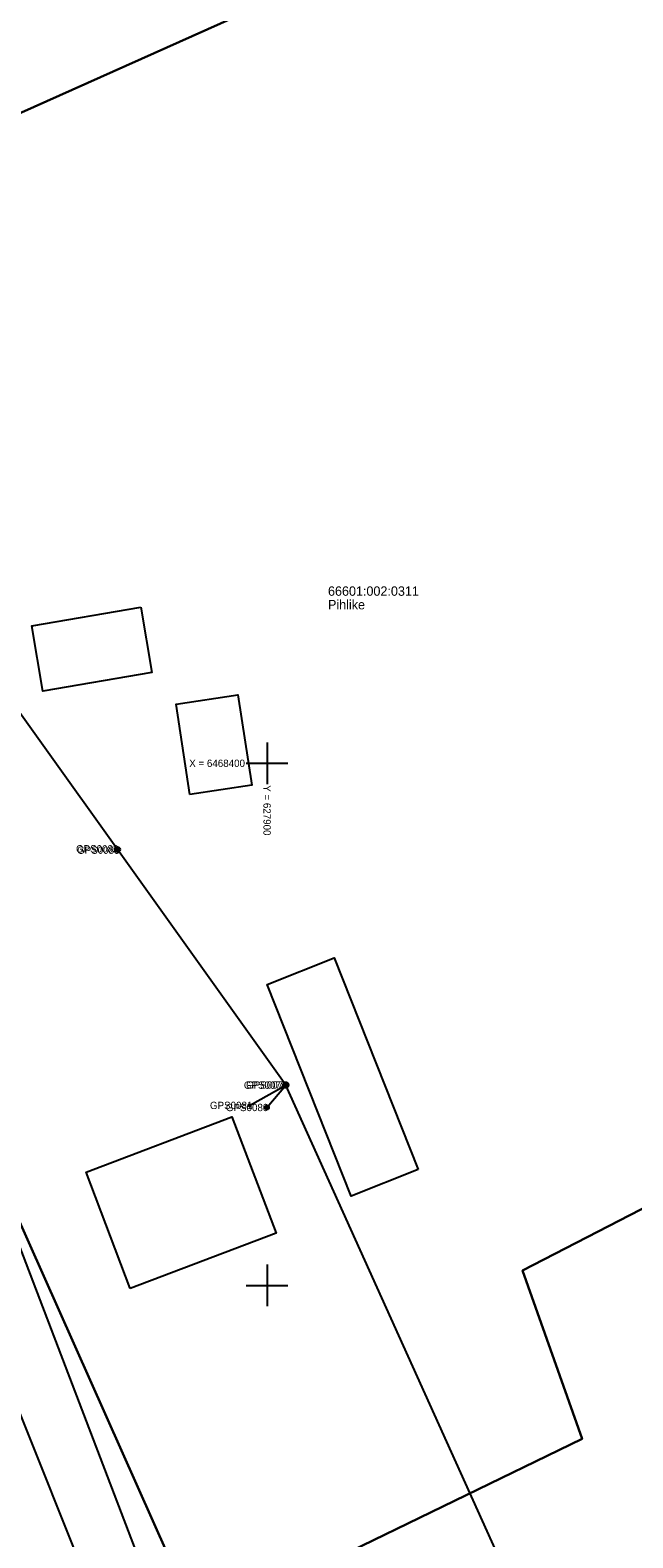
# Model space of a CAD drawing. Extents: x 626224 to 628280, y 6467750 to 6471135.
# Drawn here: x 627877.3 to 627935, y 6468325.8 to 6468470.2 of the extents above; entities that cross this region are included whole.
import ezdxf

# ---------------------------------------------------------------- set-up
doc = ezdxf.new("R2010")
doc.units = 0
for name, color, linetype in [('Hoone Elu- või ühiskondlik hoone', 7, 'Continuous'), ('Hoone Kõrval- või tootmishoone', 7, 'Continuous'), ('Maa-alune hoone Kelder', 7, 'Continuous'), ('MOOTMPUNKT', 7, 'Continuous'), ('MOOTNR', 7, 'Continuous'), ('MPOHULIIN', 7, 'Continuous'), ('PIIR', 7, 'Continuous'), ('POST', 7, 'Continuous'), ('Tee Liiklusala', 7, 'Continuous'), ('Tee Põhimaantee Püsikate', 7, 'Continuous'), ('VORK', 7, 'Continuous')]:
    doc.layers.add(name, color=color, linetype=linetype)

msp = doc.modelspace()

# ---------------------------------------------------------------- linework, layer by layer
at = {"layer": 'Hoone Elu- või ühiskondlik hoone'}
msp.add_lwpolyline([(627886.91, 6468349.7), (627882.67, 6468360.85), (627896.64, 6468366.16), (627900.87, 6468354.99)], close=True, dxfattribs=at)
at = {"layer": 'Hoone Kõrval- või tootmishoone'}
for points in [[(627887.9, 6468414.95), (627888.97, 6468408.69), (627878.55, 6468406.91), (627877.47, 6468413.16)], [(627914.47, 6468361.1), (627908.04, 6468358.55), (627900, 6468378.81), (627906.43, 6468381.36)]]:
    msp.add_lwpolyline(points, close=True, dxfattribs=at)
at = {"layer": 'Maa-alune hoone Kelder'}
msp.add_lwpolyline([(627892.59, 6468397.01), (627891.3, 6468405.67), (627897.21, 6468406.57), (627898.53, 6468397.91)], close=True, dxfattribs=at)
at = {"layer": 'MOOTMPUNKT'}
for centre in [(627885.63, 6468391.81), (627885.73, 6468391.68), (627901.7, 6468369.18), (627901.91, 6468369.2), (627898.31, 6468367.24), (627899.98, 6468367.04)]:
    msp.add_circle(centre, 0.1, dxfattribs=at)
at = {"layer": 'MPOHULIIN'}
msp.add_line((627898.31, 6468367.24), (627901.8, 6468369.19), dxfattribs=at)
msp.add_lwpolyline([(627987.7, 6468154.84), (627974.22, 6468199.23), (627965.02, 6468229.51), (627942.94, 6468278.29), (627925.23, 6468317.29), (627901.8, 6468369.19), (627885.68, 6468391.75), (627864.62, 6468421.17)], dxfattribs=at)
at = {"layer": 'PIIR'}
for points in [[(627932.6, 6468557.07), (627965.68, 6468502.25), (627838.09, 6468445.14), (627818.92, 6468478.42), (627816.33, 6468482.77), (627807.45, 6468497.75)], [(627965.68, 6468502.25), (628025.29, 6468403.44), (627924.44, 6468351.42), (627930.15, 6468335.32), (627893.5, 6468317.49), (627836.88, 6468444.6), (627838.09, 6468445.14)], [(627930.15, 6468335.32), (627924.44, 6468351.42), (628025.29, 6468403.44), (628093.6, 6468443.97), (628137.33, 6468332.21), (628082.32, 6468314.62), (628013.29, 6468289.31), (627952.14, 6468288.19), (627947, 6468286.53), (627948.23, 6468284.28), (627912.59, 6468271.79), (627893.5, 6468317.49)]]:
    msp.add_lwpolyline(points, close=True, dxfattribs=at)
msp.add_lwpolyline([(627869.05, 6468319.44), (627860.61, 6468341.12), (627850.92, 6468363.47), (627843.3, 6468381.02), (627834.21, 6468400.21), (627826.02, 6468416.53), (627816.81, 6468434.6), (627809.58, 6468448), (627801.28, 6468461.34), (627796.62, 6468466.91), (627793.68, 6468471.35), (627793.54, 6468471.56), (627816.33, 6468482.77), (627818.92, 6468478.42), (627838.09, 6468445.14), (627836.88, 6468444.6), (627893.5, 6468317.49)], dxfattribs=at)
at = {"layer": 'POST'}
msp.add_lwpolyline([(627899.98, 6468367.04), (627901.8, 6468369.19)], dxfattribs=at)
for centre, radius in [((627885.68, 6468391.75), 0.25), ((627885.68, 6468391.75), 0.0234), ((627901.8, 6468369.19), 0.25), ((627901.8, 6468369.19), 0.0234), ((627899.98, 6468367.04), 0.2)]:
    msp.add_circle(centre, radius, dxfattribs=at)
at = {"layer": 'Tee Liiklusala'}
msp.add_lwpolyline([(627760.92, 6468560.36), (627780.56, 6468531.91), (627795.19, 6468507.83), (627804.8, 6468492.03), (627819.21, 6468468.28), (627829.48, 6468450.66), (627842.63, 6468424.88), (627852.37, 6468405.79), (627854.86, 6468400.94), (627874.21, 6468359.17), (627891.81, 6468313.11), (627897.89, 6468298.46), (627907.18, 6468276.08), (627914.22, 6468258.33), (627924.31, 6468232.91), (627926.05, 6468227.94), (627930.17, 6468216.22), (627939.76, 6468188.97), (627954.88, 6468146.07), (627973.91, 6468092.36), (627984.64, 6468061.12)], dxfattribs=at)
at = {"layer": 'Tee Põhimaantee Püsikate'}
msp.add_lwpolyline([(627812.12, 6468468.85), (627818.26, 6468457.76), (627833.15, 6468430.27), (627849.46, 6468398.31), (627868.68, 6468356.83), (627882.94, 6468321.19), (627886.6, 6468311.79)], dxfattribs=at)
at = {"layer": 'VORK'}
for p, q in [((627900, 6468402), (627900, 6468398)), ((627898, 6468400), (627902, 6468400)), ((627900, 6468352), (627900, 6468348)), ((627898, 6468350), (627902, 6468350))]:
    msp.add_line(p, q, dxfattribs=at)

# ---------------------------------------------------------------- texts
at = {"layer": 'MOOTNR'}
for s, p in [('GPS0082 ', (627881.71, 6468391.46)), ('GPS0083 ', (627881.81, 6468391.33)), ('GPS0078 ', (627897.78, 6468368.83)), ('GPS0079 ', (627897.99, 6468368.85)), ('GPS0081 ', (627894.53, 6468366.89)), ('GPS0080 ', (627896.06, 6468366.69))]:
    msp.add_text(s, height=0.7, dxfattribs=at).set_placement(p)
at = {"layer": 'PIIR'}
for s, p in [('66601:002:0311', (627905.83, 6468416.04)), ('Pihlike', (627905.83, 6468414.74))]:
    msp.add_text(s, height=0.9, dxfattribs=at).set_placement(p)
at = {"layer": 'VORK'}
msp.add_text('X = 6468400', height=0.7, dxfattribs=at).set_placement((627892.55, 6468399.65))
msp.add_text('Y = 627900 ', height=0.7, rotation=270, dxfattribs=at).set_placement((627899.65, 6468397.9))

doc.saveas('drawing.dxf')
